// Mitsubishi GX Works2 project: 6个灯亮1个灯灭循环   PLC: FX3U/FX3UC

PROGRAM MAIN
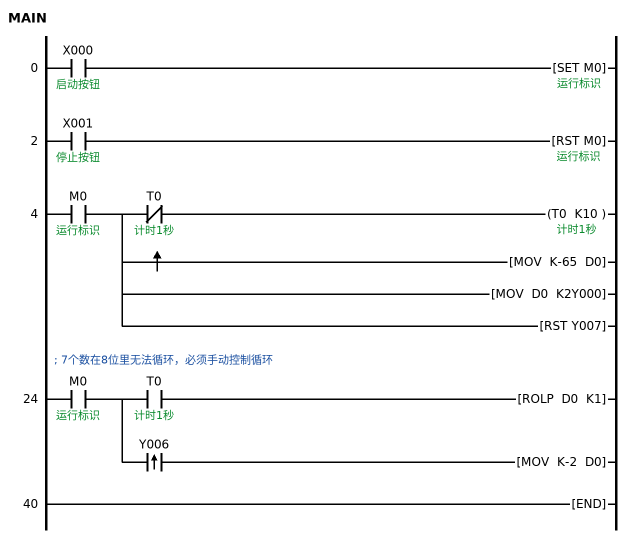
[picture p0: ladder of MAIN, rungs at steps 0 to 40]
0     LD      X000  ; 启动按钮
      SET     M0  ; 运行标识
2     LD      X001  ; 停止按钮
      RST     M0  ; 运行标识
4     LD      M0  ; 运行标识
      MPS
      ANI     T0  ; 计时1秒
      OUT     T0 K10  ; 计时1秒
      MRD
      MEP
      MOV     K-65 D0
        [note] 熄灭循环从Y6开始
      MPP
      MOV     D0 K2Y000
      RST     Y007
        [note] Y7永远不亮
; 7个数在8位里无法循环，必须手动控制循环
24    LD      M0  ; 运行标识
      MPS
      AND     T0  ; 计时1秒
      ROLP    D0 K1
        [note] 左循环
      MPP
      ANDP    Y006
      MOV     K-2 D0
        [note] Y6亮后切换回从Y0开始循环
40    END
END_PROGRAM
